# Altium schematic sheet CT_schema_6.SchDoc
size 293 x 258 mm
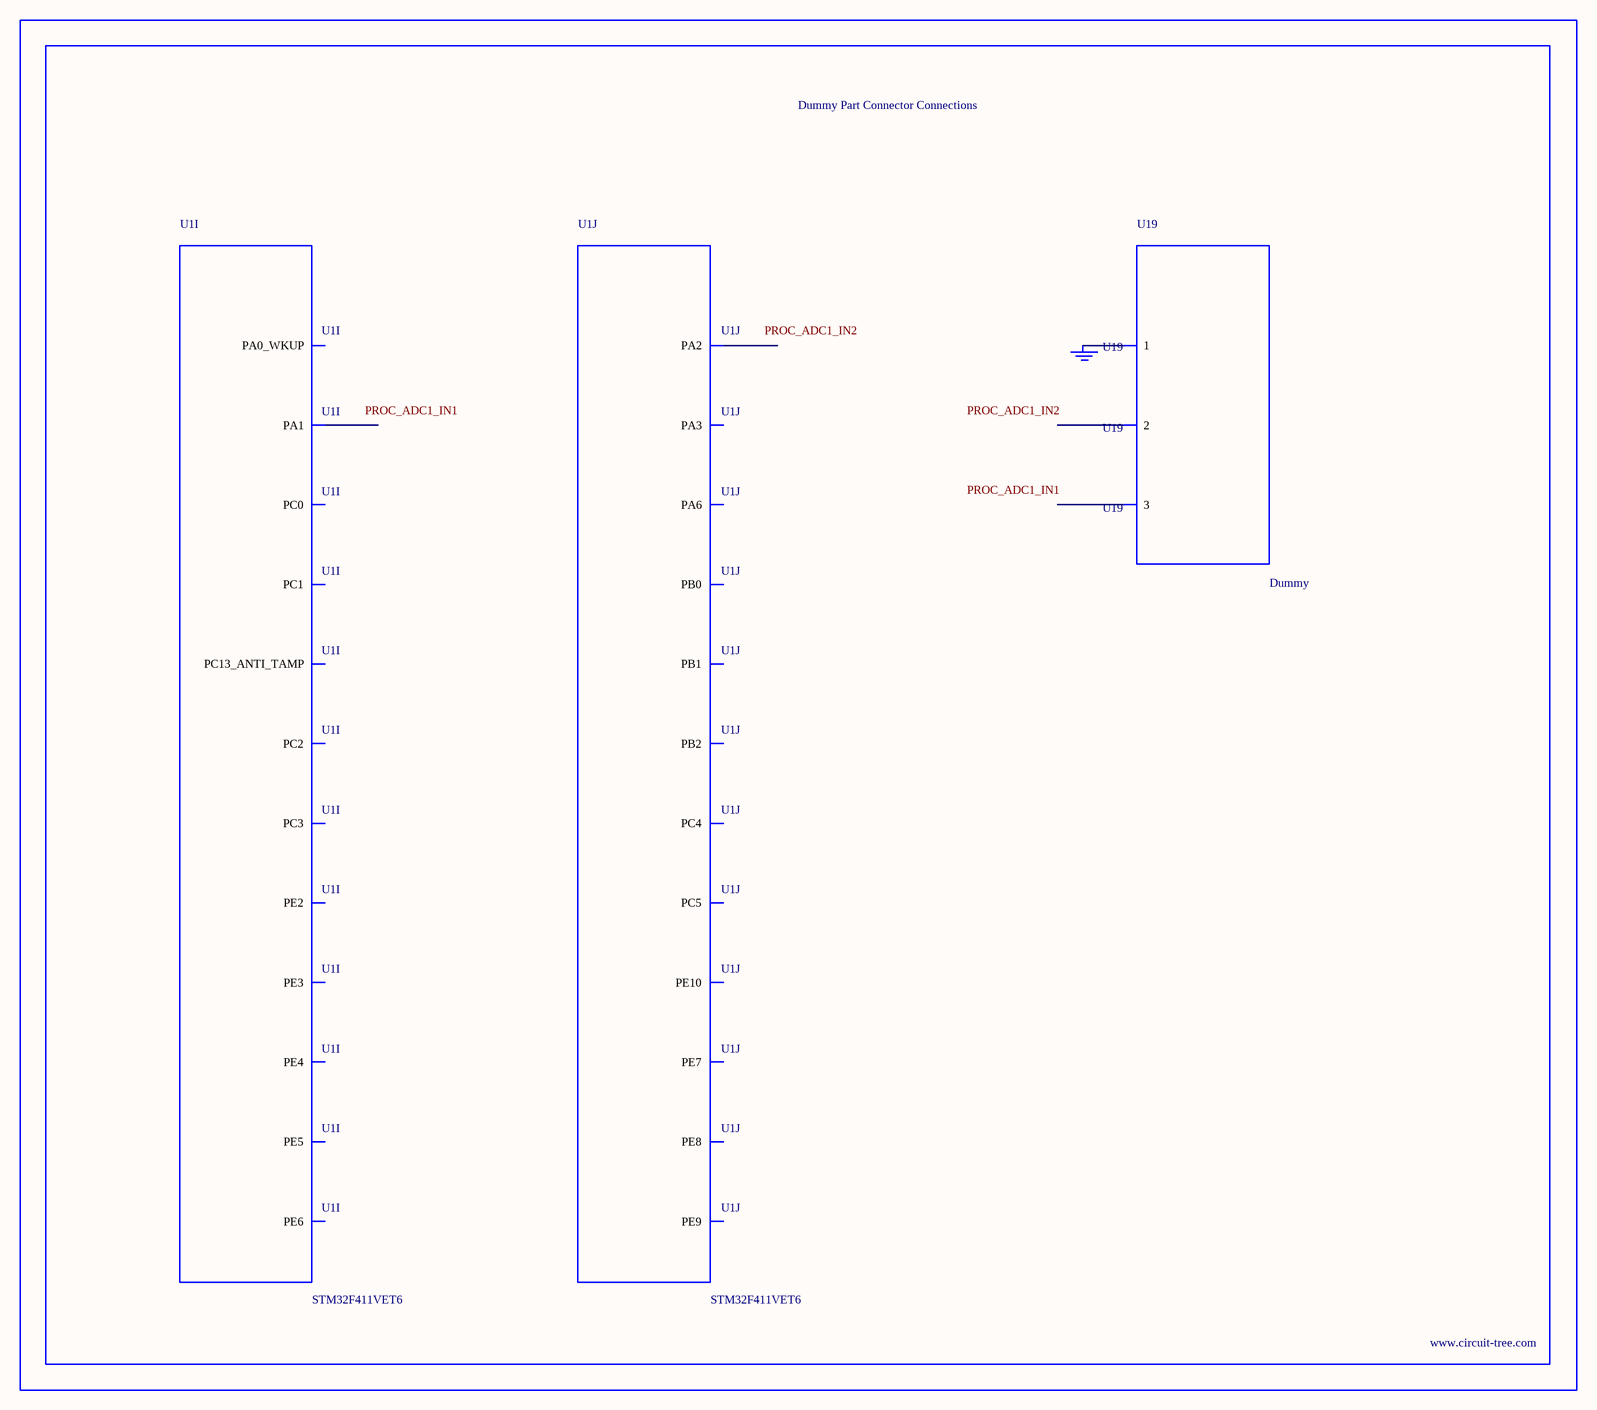
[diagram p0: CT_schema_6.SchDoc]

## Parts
BORDER5  (no value)
GND_INSTANCE_5_0  (no value)
U1  STM32F411VET6  [LQFP100]  (parts I,J of 10)
U19  Dummy  [DUMMY_PACKAGE_205]

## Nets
NetGND_INSTANCE_5_0_0: GND_INSTANCE_5_0.0(GND) U19.1

Not connected (* = marked no-connect by the designer): U1 1(PE2) 2(PE3) 3(PE4) 4(PE5) 5(PE6) 7(PC13_ANTI_TAMP) 15(PC0) 16(PC1) 17(PC2) 18(PC3) 23(PA0_WKUP) 24(PA1) 25(PA2) 26(PA3) 31(PA6) 33(PC4) 34(PC5) 35(PB0) 36(PB1) 37(PB2) 38(PE7) 39(PE8) 40(PE9) 41(PE10); U19 2 3

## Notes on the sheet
- Labels drawn without touching a wire or pin: PROC_ADC1_IN1, PROC_ADC1_IN2

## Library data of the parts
BORDER5 = BORDER_PAGE5
GND_INSTANCE_5_0 = GND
